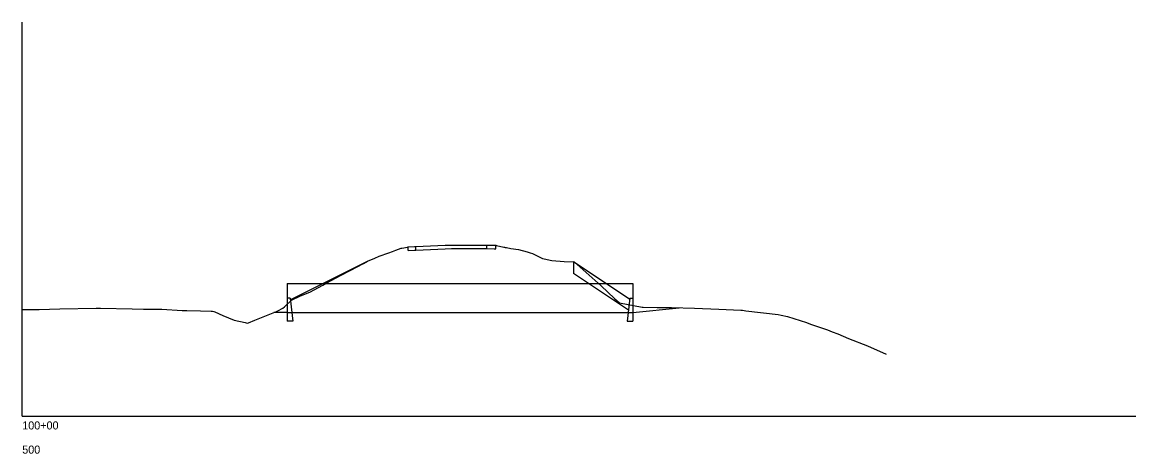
# Model space of a CAD drawing. Extents: x 2047712 to 2051245, y 280285 to 283042.
# Drawn here: x 2049041 to 2049427.6, y 282460.7 to 282610.6 of the extents above; entities that cross this region are included whole.
import ezdxf

# ---------------------------------------------------------------- set-up
doc = ezdxf.new("R2010")
doc.units = 0
for name, color, linetype in [('Default', 7, 'Continuous'), ('DR_X_Text', 7, 'Continuous'), ('PV_X_EOP', 7, 'Continuous'), ('RW_X_CL_100_Curve_Data', 7, 'Continuous'), ('SV_X_Text', 7, 'Continuous'), ('UT_X_Water_Cells', 7, 'Continuous')]:
    doc.layers.add(name, color=color, linetype=linetype)

msp = doc.modelspace()

# ---------------------------------------------------------------- linework, layer by layer
at = {"layer": 'Default'}
for q in [(2049041.01, 282610.58), (2049427.64, 282473.78)]:
    msp.add_line((2049041.01, 282473.78), q, dxfattribs=at)
at = {"layer": 'DR_X_Text'}
for p, q in [((2049134.09, 282514.14), (2049160.9, 282527.55)), ((2049253.01, 282509.78), (2049269.07, 282511.39)), ((2049133.01, 282509.78), (2049128.39, 282509.78))]:
    msp.add_line(p, q, dxfattribs=at)
at = {"layer": 'PV_X_EOP'}
for p, q in [((2049175.02, 282531.33), (2049175.02, 282532.58)), ((2049177.64, 282531.47), (2049177.64, 282532.72)), ((2049202.3, 282531.95), (2049202.3, 282533.2)), ((2049205.47, 282531.89), (2049205.47, 282533.14))]:
    msp.add_line(p, q, dxfattribs=at)
msp.add_lwpolyline([(2049175.02, 282531.33), (2049177.21, 282531.45), (2049177.64, 282531.47), (2049187.87, 282531.87), (2049190.11, 282531.95), (2049192.39, 282531.94), (2049202.3, 282531.95), (2049204.91, 282531.9), (2049205.47, 282531.89)], dxfattribs=at)
at = {"layer": 'RW_X_CL_100_Curve_Data'}
for p, q in [((2049133.01, 282519.8), (2049133.01, 282509.78)), ((2049133.01, 282519.8), (2049253.01, 282519.8)), ((2049133.01, 282519.78), (2049253.01, 282519.78)), ((2049253.01, 282519.8), (2049253.01, 282509.78)), ((2049134.01, 282514.78), (2049133.01, 282514.78)), ((2049134.01, 282514.78), (2049135.01, 282506.78)), ((2049252.01, 282514.78), (2049251.01, 282506.78)), ((2049252.01, 282514.78), (2049253.01, 282514.78)), ((2049133.01, 282509.78), (2049253.01, 282509.78)), ((2049133.01, 282509.78), (2049133.01, 282506.78)), ((2049133.01, 282509.77), (2049253.01, 282509.77)), ((2049253.01, 282509.78), (2049253.01, 282506.78)), ((2049135.01, 282506.78), (2049133.01, 282506.78)), ((2049251.01, 282506.78), (2049253.01, 282506.78))]:
    msp.add_line(p, q, dxfattribs=at)
at = {"layer": 'SV_X_Text'}
for p, q in [((2049232.37, 282527.34), (2049232.37, 282523.34)), ((2049251.95, 282514.28), (2049232.37, 282527.34)), ((2049251.49, 282510.59), (2049232.37, 282523.34))]:
    msp.add_line(p, q, dxfattribs=at)
at = {"layer": 'UT_X_Water_Cells'}
msp.add_lwpolyline([(2049041.01, 282510.8), (2049046.91, 282510.75), (2049054.1, 282510.99), (2049066.71, 282511.24), (2049067.39, 282511.26), (2049068.19, 282511.24), (2049079.22, 282511.04), (2049083.16, 282510.89), (2049089.24, 282510.86), (2049089.49, 282510.86), (2049096.48, 282510.51), (2049098.2, 282510.46), (2049102.88, 282510.33), (2049106.65, 282510.22), (2049107.01, 282510.18), (2049107.55, 282510.08), (2049107.93, 282509.98), (2049110.61, 282508.72), (2049114.62, 282507.07), (2049118.37, 282506.29), (2049118.7, 282506.17), (2049119.31, 282506.11), (2049119.57, 282506.19), (2049121.72, 282507.04), (2049129.25, 282510.14), (2049129.74, 282510.31), (2049131.53, 282511.25), (2049132.1, 282511.77), (2049134.5, 282514.08), (2049137.39, 282515.44), (2049139.32, 282516.19), (2049140.81, 282516.84), (2049145.39, 282519.28), (2049146.8, 282520.08), (2049151.5, 282522.63), (2049155.08, 282524.45), (2049159.51, 282526.81), (2049160.9, 282527.55), (2049163.44, 282528.69), (2049164.92, 282529.35), (2049168.25, 282530.47), (2049169.54, 282530.9), (2049170.71, 282531.37), (2049172.54, 282532.08), (2049172.75, 282532.1), (2049172.8, 282532.11), (2049174.74, 282532.51), (2049175.02, 282532.58), (2049177.21, 282532.7), (2049177.64, 282532.72), (2049187.87, 282533.12), (2049190.11, 282533.2), (2049192.39, 282533.19), (2049202.3, 282533.2), (2049204.91, 282533.15), (2049205.47, 282533.14), (2049205.63, 282533.06), (2049208.19, 282532.47), (2049208.49, 282532.45), (2049208.66, 282532.38), (2049209.12, 282532.31), (2049210.68, 282532.01), (2049213.33, 282531.66), (2049216.3, 282530.83), (2049216.73, 282530.71), (2049217.4, 282530.51), (2049218.23, 282530.2), (2049221.65, 282528.52), (2049222.21, 282528.43), (2049224.94, 282527.83), (2049229.19, 282527.47), (2049232.64, 282527.32), (2049242.03, 282518.98), (2049246.64, 282514.65), (2049248.42, 282513.11), (2049256.21, 282511.64), (2049256.45, 282511.59), (2049256.53, 282511.58), (2049256.58, 282511.58), (2049261.49, 282511.51), (2049265.2, 282511.46), (2049265.31, 282511.46), (2049266.41, 282511.44), (2049274.39, 282511.29), (2049282.9, 282510.91), (2049290.47, 282510.59), (2049291.07, 282510.55), (2049291.62, 282510.47), (2049292.22, 282510.35), (2049303.49, 282509.08), (2049304.56, 282508.79), (2049306.74, 282508.33), (2049313.32, 282506.26), (2049314.73, 282505.74), (2049320.67, 282503.78), (2049322.28, 282503), (2049324.15, 282502.36), (2049327.86, 282500.72), (2049334.54, 282498.14), (2049341.01, 282495.33)], dxfattribs=at)

# ---------------------------------------------------------------- texts
at = {"layer": 'Default'}
for s, p in [('100+00', (2049041.01, 282469.13)), ('500', (2049041.01, 282460.73))]:
    msp.add_text(s, height=2.8, dxfattribs=at).set_placement(p)

doc.saveas('drawing.dxf')
